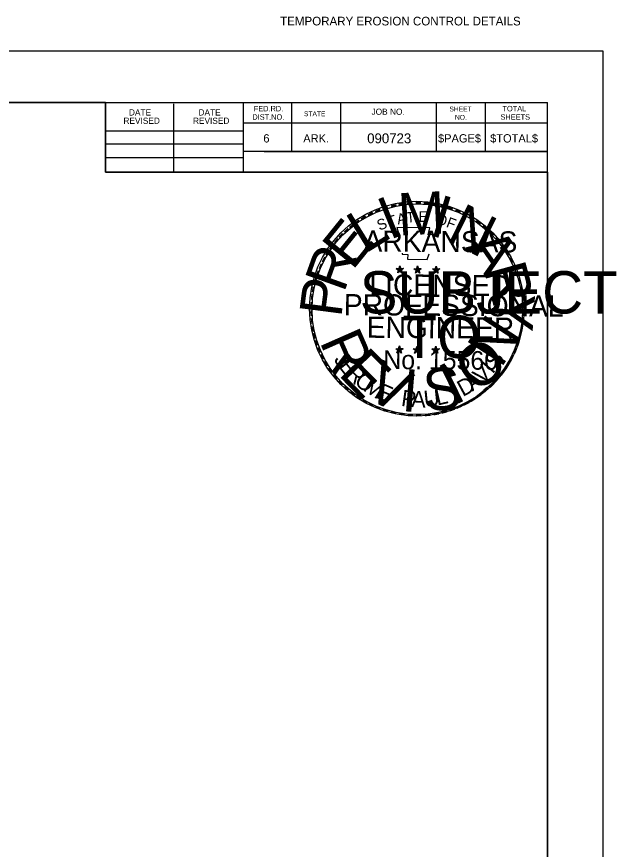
# Model space of a CAD drawing. Extents: x 60284.6 to 60318.8, y 53662.9 to 53686.5.
# Drawn here: x 60310.3 to 60318.8, y 53674.66 to 53686.45 of the extents above; entities that cross this region are included whole.
import ezdxf

# ---------------------------------------------------------------- set-up
doc = ezdxf.new("R2010")
doc.units = 0
for name, color, linetype in [('Level 1', 7, 'Continuous'), ('Level 38', 7, 'Continuous'), ('Level 49', 7, 'Continuous'), ('Level 62', 7, 'Continuous'), ('Level 63', 7, 'Continuous'), ('R_Border', 7, 'Continuous'), ('R_No Plot', 7, 'Continuous'), ('Stamp Mask', 7, 'Continuous'), ('TYPICAL FONT', 7, 'Continuous')]:
    doc.layers.add(name, color=color, linetype=linetype)

msp = doc.modelspace()

# ---------------------------------------------------------------- linework, layer by layer
at = {"layer": 'Level 1'}
for p, q in [((60286.201, 53685.237), (60317.819, 53685.237)), ((60311.555, 53684.249), (60311.555, 53685.237)), ((60312.523, 53684.249), (60312.523, 53685.217)), ((60313.509, 53685.237), (60313.509, 53684.249)), ((60314.193, 53685.237), (60314.193, 53684.543)), ((60314.887, 53685.237), (60314.887, 53684.543)), ((60316.245, 53685.237), (60316.245, 53684.543)), ((60316.939, 53685.237), (60316.939, 53684.543)), ((60317.819, 53664.691), (60317.819, 53685.237)), ((60311.555, 53684.835), (60313.509, 53684.835)), ((60317.819, 53684.943), (60313.509, 53684.943)), ((60317.819, 53684.945), (60317.819, 53684.945)), ((60311.555, 53684.649), (60313.509, 53684.649)), ((60317.819, 53684.543), (60313.509, 53684.543)), ((60313.805, 53684.543), (60317.819, 53684.543)), ((60311.555, 53684.455), (60313.509, 53684.455)), ((60317.819, 53684.249), (60311.555, 53684.249))]:
    msp.add_line(p, q, dxfattribs=at)
at = {"layer": 'Level 38'}
msp.add_lwpolyline([(60286.201, 53664.691), (60286.201, 53685.237), (60311.555, 53685.237), (60311.555, 53684.249), (60313.201, 53684.249), (60313.509, 53684.249), (60313.509, 53684.249), (60313.509, 53684.249), (60317.819, 53684.249), (60317.819, 53683.957), (60317.819, 53680.626), (60317.819, 53664.691)], close=True, dxfattribs=at)
at = {"layer": 'Level 49'}
for p, q in [((60315.676, 53682.883), (60315.73, 53682.866)), ((60315.676, 53682.883), (60315.715, 53682.881)), ((60315.676, 53682.883), (60315.715, 53682.879)), ((60315.676, 53682.883), (60315.711, 53682.874)), ((60315.676, 53682.883), (60315.711, 53682.868)), ((60315.676, 53682.883), (60315.711, 53682.866)), ((60315.676, 53682.883), (60315.711, 53682.861)), ((60315.698, 53682.822), (60315.73, 53682.866)), ((60315.698, 53682.822), (60315.711, 53682.864)), ((60315.698, 53682.822), (60315.715, 53682.859)), ((60315.698, 53682.822), (60315.717, 53682.857)), ((60315.698, 53682.822), (60315.722, 53682.853)), ((60315.698, 53682.822), (60315.73, 53682.853)), ((60315.698, 53682.822), (60315.73, 53682.85)), ((60315.73, 53682.924), (60315.722, 53682.883)), ((60315.73, 53682.924), (60315.722, 53682.887)), ((60315.73, 53682.924), (60315.726, 53682.887)), ((60315.73, 53682.866), (60315.73, 53682.924)), ((60315.73, 53682.924), (60315.739, 53682.883)), ((60315.73, 53682.924), (60315.737, 53682.887)), ((60315.73, 53682.924), (60315.732, 53682.887)), ((60315.782, 53682.883), (60315.73, 53682.866)), ((60315.761, 53682.82), (60315.73, 53682.866)), ((60315.761, 53682.82), (60315.73, 53682.853)), ((60315.761, 53682.82), (60315.73, 53682.85)), ((60315.782, 53682.883), (60315.733, 53682.879)), ((60315.761, 53682.82), (60315.733, 53682.853)), ((60315.782, 53682.883), (60315.739, 53682.875)), ((60315.782, 53682.883), (60315.739, 53682.872)), ((60315.761, 53682.82), (60315.739, 53682.864)), ((60315.761, 53682.82), (60315.739, 53682.859)), ((60315.761, 53682.82), (60315.745, 53682.866)), ((60315.782, 53682.883), (60315.746, 53682.872)), ((60315.782, 53682.883), (60315.752, 53682.868)), ((60315.782, 53682.883), (60315.754, 53682.866)), ((60315.926, 53682.881), (60315.979, 53682.866)), ((60315.926, 53682.881), (60315.964, 53682.879)), ((60315.926, 53682.881), (60315.964, 53682.875)), ((60315.926, 53682.881), (60315.964, 53682.874)), ((60315.926, 53682.881), (60315.963, 53682.866)), ((60315.926, 53682.881), (60315.963, 53682.864)), ((60315.926, 53682.881), (60315.963, 53682.859)), ((60315.948, 53682.82), (60315.979, 53682.866)), ((60315.948, 53682.82), (60315.964, 53682.861)), ((60315.948, 53682.82), (60315.964, 53682.859)), ((60315.948, 53682.82), (60315.966, 53682.857)), ((60315.948, 53682.82), (60315.972, 53682.851)), ((60315.948, 53682.82), (60315.979, 53682.851)), ((60315.948, 53682.82), (60315.979, 53682.85)), ((60315.979, 53682.92), (60315.972, 53682.881)), ((60315.979, 53682.92), (60315.972, 53682.883)), ((60315.979, 53682.92), (60315.974, 53682.883)), ((60315.979, 53682.866), (60315.979, 53682.92)), ((60315.979, 53682.92), (60315.988, 53682.881)), ((60315.979, 53682.92), (60315.987, 53682.883)), ((60315.979, 53682.92), (60315.981, 53682.883)), ((60316.031, 53682.881), (60315.979, 53682.866)), ((60316.011, 53682.82), (60315.979, 53682.866)), ((60316.011, 53682.82), (60315.979, 53682.851)), ((60316.011, 53682.82), (60315.979, 53682.85)), ((60316.031, 53682.881), (60315.985, 53682.879)), ((60316.011, 53682.82), (60315.985, 53682.851)), ((60316.031, 53682.881), (60315.988, 53682.874)), ((60316.031, 53682.881), (60315.988, 53682.872)), ((60316.011, 53682.82), (60315.988, 53682.864)), ((60316.011, 53682.82), (60315.988, 53682.857)), ((60316.011, 53682.82), (60315.994, 53682.864)), ((60316.031, 53682.881), (60315.996, 53682.868)), ((60316.031, 53682.881), (60316.001, 53682.866)), ((60316.031, 53682.881), (60316.003, 53682.864)), ((60316.19, 53682.879), (60316.244, 53682.861)), ((60316.19, 53682.879), (60316.232, 53682.874)), ((60316.19, 53682.879), (60316.229, 53682.872)), ((60316.19, 53682.879), (60316.229, 53682.868)), ((60316.19, 53682.879), (60316.227, 53682.864)), ((60316.19, 53682.879), (60316.227, 53682.859)), ((60316.19, 53682.879), (60316.227, 53682.859)), ((60316.21, 53682.818), (60316.244, 53682.861)), ((60316.21, 53682.818), (60316.229, 53682.859)), ((60316.21, 53682.818), (60316.232, 53682.853)), ((60316.21, 53682.818), (60316.232, 53682.851)), ((60316.21, 53682.818), (60316.244, 53682.851)), ((60316.21, 53682.818), (60316.24, 53682.85)), ((60316.21, 53682.818), (60316.247, 53682.844)), ((60316.244, 53682.916), (60316.234, 53682.881)), ((60316.244, 53682.916), (60316.24, 53682.879)), ((60316.244, 53682.916), (60316.24, 53682.879)), ((60316.244, 53682.861), (60316.244, 53682.916)), ((60316.244, 53682.916), (60316.255, 53682.879)), ((60316.244, 53682.916), (60316.251, 53682.879)), ((60316.244, 53682.916), (60316.247, 53682.879)), ((60316.295, 53682.879), (60316.244, 53682.861)), ((60316.273, 53682.818), (60316.244, 53682.861)), ((60316.273, 53682.818), (60316.244, 53682.851)), ((60316.273, 53682.818), (60316.244, 53682.844)), ((60316.295, 53682.879), (60316.249, 53682.874)), ((60316.273, 53682.818), (60316.249, 53682.85)), ((60316.295, 53682.879), (60316.255, 53682.872)), ((60316.295, 53682.879), (60316.255, 53682.866)), ((60316.273, 53682.818), (60316.255, 53682.859)), ((60316.273, 53682.818), (60316.255, 53682.853)), ((60316.273, 53682.818), (60316.258, 53682.859)), ((60316.295, 53682.879), (60316.262, 53682.864)), ((60316.295, 53682.879), (60316.264, 53682.864)), ((60316.295, 53682.879), (60316.269, 53682.861)), ((60315.722, 53681.789), (60315.711, 53681.752)), ((60315.722, 53681.789), (60315.715, 53681.748)), ((60315.722, 53681.789), (60315.717, 53681.748)), ((60315.722, 53681.732), (60315.722, 53681.789)), ((60315.722, 53681.789), (60315.73, 53681.748)), ((60315.722, 53681.789), (60315.73, 53681.748)), ((60315.722, 53681.789), (60315.722, 53681.748)), ((60315.972, 53681.785), (60315.963, 53681.748)), ((60315.972, 53681.785), (60315.964, 53681.748)), ((60315.972, 53681.785), (60315.966, 53681.748)), ((60315.972, 53681.732), (60315.972, 53681.785)), ((60315.972, 53681.785), (60315.979, 53681.746)), ((60315.972, 53681.785), (60315.979, 53681.746)), ((60315.972, 53681.785), (60315.972, 53681.748)), ((60316.236, 53681.783), (60316.227, 53681.744)), ((60316.236, 53681.783), (60316.229, 53681.744)), ((60316.236, 53681.783), (60316.232, 53681.744)), ((60316.236, 53681.726), (60316.236, 53681.783)), ((60316.236, 53681.783), (60316.244, 53681.744)), ((60316.236, 53681.783), (60316.244, 53681.744)), ((60316.236, 53681.783), (60316.236, 53681.744)), ((60315.669, 53681.748), (60315.722, 53681.732)), ((60315.669, 53681.748), (60315.708, 53681.746)), ((60315.669, 53681.748), (60315.706, 53681.741)), ((60315.669, 53681.748), (60315.706, 53681.741)), ((60315.669, 53681.748), (60315.706, 53681.733)), ((60315.669, 53681.748), (60315.706, 53681.732)), ((60315.669, 53681.748), (60315.706, 53681.73)), ((60315.687, 53681.691), (60315.722, 53681.732)), ((60315.687, 53681.691), (60315.706, 53681.732)), ((60315.687, 53681.691), (60315.708, 53681.724)), ((60315.687, 53681.691), (60315.709, 53681.724)), ((60315.687, 53681.691), (60315.722, 53681.722)), ((60315.687, 53681.691), (60315.715, 53681.719)), ((60315.687, 53681.691), (60315.722, 53681.717)), ((60315.752, 53681.687), (60315.719, 53681.717)), ((60315.774, 53681.748), (60315.722, 53681.732)), ((60315.752, 53681.687), (60315.722, 53681.732)), ((60315.752, 53681.687), (60315.722, 53681.719)), ((60315.752, 53681.687), (60315.724, 53681.719)), ((60315.774, 53681.748), (60315.726, 53681.746)), ((60315.774, 53681.748), (60315.73, 53681.741)), ((60315.774, 53681.748), (60315.73, 53681.739)), ((60315.752, 53681.687), (60315.73, 53681.732)), ((60315.752, 53681.687), (60315.73, 53681.724)), ((60315.774, 53681.748), (60315.737, 53681.737)), ((60315.752, 53681.687), (60315.737, 53681.732)), ((60315.774, 53681.748), (60315.741, 53681.733)), ((60315.774, 53681.748), (60315.745, 53681.732)), ((60315.918, 53681.748), (60315.972, 53681.732)), ((60315.918, 53681.748), (60315.957, 53681.744)), ((60315.918, 53681.748), (60315.957, 53681.741)), ((60315.918, 53681.748), (60315.957, 53681.739)), ((60315.918, 53681.748), (60315.955, 53681.733)), ((60315.918, 53681.748), (60315.955, 53681.73)), ((60315.918, 53681.748), (60315.955, 53681.726)), ((60315.937, 53681.687), (60315.972, 53681.732)), ((60315.937, 53681.687), (60315.957, 53681.73)), ((60315.937, 53681.687), (60315.957, 53681.722)), ((60315.937, 53681.687), (60315.959, 53681.722)), ((60315.937, 53681.687), (60315.964, 53681.719)), ((60315.937, 53681.687), (60315.972, 53681.719)), ((60315.937, 53681.687), (60315.972, 53681.715)), ((60316.001, 53681.687), (60315.97, 53681.715)), ((60316.022, 53681.746), (60315.972, 53681.732)), ((60316.001, 53681.687), (60315.972, 53681.732)), ((60316.001, 53681.687), (60315.972, 53681.719)), ((60316.001, 53681.687), (60315.974, 53681.719)), ((60316.022, 53681.746), (60315.977, 53681.746)), ((60316.022, 53681.746), (60315.979, 53681.739)), ((60316.022, 53681.746), (60315.979, 53681.739)), ((60316.001, 53681.687), (60315.979, 53681.73)), ((60316.001, 53681.687), (60315.979, 53681.724)), ((60316.022, 53681.746), (60315.987, 53681.733)), ((60316.001, 53681.687), (60315.987, 53681.73)), ((60316.022, 53681.746), (60315.992, 53681.732)), ((60316.022, 53681.746), (60315.994, 53681.73)), ((60316.183, 53681.744), (60316.236, 53681.726)), ((60316.183, 53681.744), (60316.221, 53681.741)), ((60316.183, 53681.744), (60316.221, 53681.737)), ((60316.183, 53681.744), (60316.219, 53681.733)), ((60316.183, 53681.744), (60316.219, 53681.73)), ((60316.183, 53681.744), (60316.218, 53681.726)), ((60316.183, 53681.744), (60316.218, 53681.722)), ((60316.203, 53681.683), (60316.236, 53681.726)), ((60316.203, 53681.683), (60316.219, 53681.726)), ((60316.203, 53681.683), (60316.221, 53681.719)), ((60316.203, 53681.683), (60316.225, 53681.719)), ((60316.203, 53681.683), (60316.229, 53681.715)), ((60316.203, 53681.683), (60316.234, 53681.715)), ((60316.203, 53681.683), (60316.236, 53681.711)), ((60316.266, 53681.683), (60316.234, 53681.715)), ((60316.266, 53681.683), (60316.234, 53681.711)), ((60316.288, 53681.744), (60316.236, 53681.726)), ((60316.266, 53681.683), (60316.236, 53681.726)), ((60316.266, 53681.683), (60316.24, 53681.715)), ((60316.288, 53681.744), (60316.242, 53681.741)), ((60316.288, 53681.744), (60316.244, 53681.737)), ((60316.288, 53681.744), (60316.244, 53681.733)), ((60316.266, 53681.683), (60316.244, 53681.719)), ((60316.266, 53681.683), (60316.247, 53681.726)), ((60316.266, 53681.683), (60316.249, 53681.726)), ((60316.288, 53681.744), (60316.255, 53681.732)), ((60316.288, 53681.744), (60316.256, 53681.726)), ((60316.288, 53681.744), (60316.258, 53681.726))]:
    msp.add_line(p, q, dxfattribs=at)
for points in [[(60315.687, 53683.465), (60315.724, 53683.339)], [(60316.212, 53683.323), (60316.234, 53683.367), (60316.129, 53683.362), (60316.153, 53683.461), (60315.687, 53683.465)], [(60315.759, 53683.101), (60315.759, 53683.086), (60315.842, 53683.084), (60315.835, 53683.016), (60316.114, 53683.014), (60316.144, 53683.092)], [(60315.73, 53682.924), (60315.761, 53682.82), (60315.676, 53682.883), (60315.782, 53682.883), (60315.698, 53682.822), (60315.73, 53682.924)], [(60315.979, 53682.92), (60316.011, 53682.82), (60315.926, 53682.881), (60316.031, 53682.881), (60315.948, 53682.82), (60315.979, 53682.92)], [(60316.244, 53682.916), (60316.273, 53682.818), (60316.19, 53682.879), (60316.295, 53682.879), (60316.21, 53682.818), (60316.244, 53682.916)], [(60315.722, 53681.789), (60315.752, 53681.687), (60315.669, 53681.748), (60315.774, 53681.748), (60315.687, 53681.691), (60315.722, 53681.789)], [(60315.972, 53681.785), (60316.001, 53681.687), (60315.918, 53681.748), (60316.022, 53681.746), (60315.937, 53681.687), (60315.972, 53681.785)], [(60316.236, 53681.783), (60316.266, 53681.683), (60316.183, 53681.744), (60316.288, 53681.744), (60316.203, 53681.683), (60316.236, 53681.783)], [(60316.929, 53681.144), (60316.922, 53681.168), (60316.966, 53681.205)], [(60316.962, 53681.21), (60316.97, 53681.188), (60316.925, 53681.149)], [(60316.97, 53681.192), (60316.925, 53681.153)], [(60316.97, 53681.188), (60316.927, 53681.151)]]:
    msp.add_lwpolyline(points, dxfattribs=at)
for centre, radius in [((60315.731, 53682.865), 0.0258), ((60315.731, 53682.865), 0.0233), ((60315.731, 53682.865), 0.0216), ((60315.731, 53682.865), 0.0199), ((60315.731, 53682.865), 0.0173), ((60315.731, 53682.865), 0.0161), ((60315.731, 53682.865), 0.0148), ((60315.731, 53682.865), 0.0128), ((60315.731, 53682.865), 0.0112), ((60315.731, 53682.865), 0.0093), ((60315.731, 53682.865), 0.00742), ((60315.731, 53682.865), 0.00553), ((60315.731, 53682.865), 0.00444), ((60315.731, 53682.865), 0.00216), ((60315.981, 53682.864), 0.0258), ((60315.981, 53682.864), 0.0233), ((60315.981, 53682.864), 0.0216), ((60315.981, 53682.864), 0.0199), ((60315.981, 53682.864), 0.0173), ((60315.981, 53682.864), 0.0161), ((60315.981, 53682.864), 0.0148), ((60315.981, 53682.864), 0.0128), ((60315.981, 53682.864), 0.0112), ((60315.981, 53682.864), 0.0093), ((60315.981, 53682.864), 0.00742), ((60315.981, 53682.864), 0.00553), ((60315.981, 53682.864), 0.00444), ((60315.981, 53682.864), 0.00216), ((60316.245, 53682.86), 0.0258), ((60316.245, 53682.86), 0.0233), ((60316.245, 53682.86), 0.0216), ((60316.245, 53682.86), 0.0199), ((60316.245, 53682.86), 0.0173), ((60316.245, 53682.86), 0.0161), ((60316.245, 53682.86), 0.0148), ((60316.245, 53682.86), 0.0128), ((60316.245, 53682.86), 0.0112), ((60316.245, 53682.86), 0.0093), ((60316.245, 53682.86), 0.00742), ((60316.245, 53682.86), 0.00553), ((60316.245, 53682.86), 0.00444), ((60316.245, 53682.86), 0.00216), ((60315.722, 53681.731), 0.0258), ((60315.722, 53681.731), 0.0233), ((60315.722, 53681.731), 0.0216), ((60315.722, 53681.731), 0.0199), ((60315.722, 53681.731), 0.0173), ((60315.722, 53681.731), 0.0161), ((60315.722, 53681.731), 0.0148), ((60315.722, 53681.731), 0.0128), ((60315.722, 53681.731), 0.0112), ((60315.722, 53681.731), 0.0093), ((60315.722, 53681.731), 0.00742), ((60315.722, 53681.731), 0.00553), ((60315.722, 53681.731), 0.00444), ((60315.722, 53681.731), 0.00216), ((60315.972, 53681.73), 0.0258), ((60315.972, 53681.73), 0.0233), ((60315.972, 53681.73), 0.0216), ((60315.972, 53681.73), 0.0199), ((60315.972, 53681.73), 0.0173), ((60315.972, 53681.73), 0.0161), ((60315.972, 53681.73), 0.0148), ((60315.972, 53681.73), 0.0128), ((60315.972, 53681.73), 0.0112), ((60315.972, 53681.73), 0.0093), ((60315.972, 53681.73), 0.00742), ((60315.972, 53681.73), 0.00553), ((60315.972, 53681.73), 0.00444), ((60315.972, 53681.73), 0.00216), ((60316.237, 53681.726), 0.0258), ((60316.237, 53681.726), 0.0233), ((60316.237, 53681.726), 0.0216), ((60316.237, 53681.726), 0.0199), ((60316.237, 53681.726), 0.0173), ((60316.237, 53681.726), 0.0161), ((60316.237, 53681.726), 0.0148), ((60316.237, 53681.726), 0.0128), ((60316.237, 53681.726), 0.0112), ((60316.237, 53681.726), 0.0093), ((60316.237, 53681.726), 0.00742), ((60316.237, 53681.726), 0.00553), ((60316.237, 53681.726), 0.00444), ((60316.237, 53681.726), 0.00216)]:
    msp.add_circle(centre, radius, dxfattribs=at)
at = {"layer": 'Level 62'}
msp.add_circle((60315.976, 53682.306), 1.492, dxfattribs=at)
at = {"layer": 'Level 63'}
msp.add_lwpolyline([(60284.604, 53685.965), (60318.604, 53685.965), (60318.604, 53663.965), (60284.604, 53663.965)], close=True, dxfattribs=at)
at = {"layer": 'R_No Plot'}
msp.add_lwpolyline([(60317.819, 53674.964), (60317.819, 53684.249), (60311.555, 53684.249), (60311.555, 53685.237), (60286.201, 53685.237), (60286.201, 53664.691), (60303.668, 53664.691), (60317.819, 53664.691)], close=True, dxfattribs=at)
at = {"layer": 'Stamp Mask'}
msp.add_circle((60315.969, 53682.315), 1.521, dxfattribs=at)

# ---------------------------------------------------------------- texts
at = {"layer": 'Level 1'}
for s, height, p in [('TOTAL', 0.0782, (60317.183, 53685.109)), ('DATE', 0.0879, (60311.888, 53685.051)), ('DATE', 0.0879, (60312.874, 53685.051)), ('DIST.NO.', 0.0782, (60313.637, 53684.991)), ('FED.RD.', 0.0782, (60313.657, 53685.109)), ('STATE', 0.0684, (60314.369, 53685.041)), ('JOB NO.', 0.0879, (60315.327, 53685.061)), ('SHEET', 0.0684, (60316.431, 53685.109)), ('SHEETS', 0.0782, (60317.155, 53684.991)), ('REVISED', 0.0879, (60311.81, 53684.933)), ('REVISED', 0.0879, (60312.796, 53684.933)), ('NO.', 0.0684, (60316.509, 53684.991)), ('6', 0.117, (60313.793, 53684.669)), ('ARK.', 0.1172, (60314.359, 53684.669)), ('090723', 0.14, (60315.265, 53684.658)), ('$PAGE$', 0.1172, (60316.269, 53684.669)), ('$TOTAL$', 0.1172, (60317.008, 53684.669))]:
    msp.add_text(s, height=height, dxfattribs=at).set_placement(p)
at = {"layer": 'Level 49'}
for s, height, rotation, p in [('-', 0.24, 13.2326, (60315.611, 53683.672)), ('-', 0.24, 9.8217, (60315.711, 53683.696)), ('-', 0.24, 5.4992, (60315.822, 53683.711)), ('-', 0.24, 359.7886, (60315.937, 53683.722)), ('-', 0.24, 357.3454, (60316.048, 53683.718)), ('-', 0.24, 351.7641, (60316.157, 53683.709)), ('-', 0.24, 346.8073, (60316.266, 53683.692)), ('-', 0.24, 28.3942, (60315.308, 53683.55)), ('-', 0.24, 23.9096, (60315.403, 53683.596)), ('-', 0.24, 18.7785, (60315.499, 53683.637)), ('A', 0.15, 10.8156, (60315.7, 53683.506)), ('T', 0.15, 5.6252, (60315.828, 53683.53)), ('E', 0.15, 0.4347, (60315.992, 53683.544)), ('-', 0.24, 341.9386, (60316.36, 53683.666)), ('-', 0.24, 337.4575, (60316.469, 53683.633)), ('-', 0.24, 333.7235, (60316.565, 53683.594)), ('-', 0.24, 35.8341, (60315.131, 53683.437)), ('-', 0.24, 33.666, (60315.218, 53683.496)), ('S', 0.15, 21.1964, (60315.438, 53683.419)), ('T', 0.15, 16.006, (60315.575, 53683.469)), ('O', 0.15, 350.0539, (60316.232, 53683.513)), ('F', 0.15, 339.6731, (60316.375, 53683.476)), ('-', 0.24, 329.2433, (60316.65, 53683.55)), ('-', 0.24, 325.4651, (60316.746, 53683.493)), ('-', 0.24, 42.5646, (60314.994, 53683.319)), ('-', 0.24, 38.5531, (60315.061, 53683.38)), ('ARKANSAS', 0.2995, 359.6024, (60315.212, 53683.125)), ('-', 0.24, 320.1321, (60316.837, 53683.43)), ('-', 0.24, 315.181, (60316.927, 53683.356)), ('-', 0.24, 50.2166, (60314.865, 53683.177)), ('-', 0.24, 48.0254, (60314.926, 53683.249)), ('-', 0.24, 309.4821, (60317.01, 53683.273)), ('-', 0.24, 53.8349, (60314.802, 53683.092)), ('-', 0.24, 306.2546, (60317.086, 53683.182)), ('-', 0.24, 57.673, (60314.754, 53683.01)), ('-', 0.21, 303.2777, (60317.16, 53683.095)), ('-', 0.24, 67.3767, (60314.669, 53682.829)), ('-', 0.24, 62.4738, (60314.708, 53682.92)), ('-', 0.24, 299.2708, (60317.206, 53683.005)), ('-', 0.24, 71.9969, (60314.634, 53682.735)), ('-', 0.24, 294.2652, (60317.254, 53682.912)), ('-', 0.24, 290.1752, (60317.295, 53682.829)), ('-', 0.24, 75.0634, (60314.604, 53682.628)), ('LICENSED', 0.2995, 359.6024, (60315.296, 53682.505)), ('-', 0.24, 284.7257, (60317.326, 53682.741)), ('-', 0.24, 80.8037, (60314.582, 53682.522)), ('-', 0.24, 280.1517, (60317.356, 53682.628)), ('-', 0.24, 84.7887, (60314.571, 53682.419)), ('PROFESSIONAL', 0.29945, 359.6024, (60314.933, 53682.223)), ('-', 0.24, 276.1986, (60317.382, 53682.513)), ('-', 0.24, 88.6646, (60314.567, 53682.314)), ('-', 0.24, 273.9325, (60317.389, 53682.404)), ('-', 0.24, 93.7983, (60314.571, 53682.205)), ('-', 0.24, 269.5431, (60317.393, 53682.312)), ('-', 0.24, 98.5503, (60314.582, 53682.103)), ('ENGINEER', 0.2995, 359.6024, (60315.257, 53681.903)), ('-', 0.24, 263.1196, (60317.389, 53682.212)), ('-', 0.24, 101.3173, (60314.599, 53681.994)), ('-', 0.24, 260.5977, (60317.376, 53682.114)), ('-', 0.24, 105.0602, (60314.625, 53681.905)), ('-', 0.24, 255.365, (60317.36, 53682.012)), ('-', 0.24, 108.6898, (60314.656, 53681.813)), ('-', 0.24, 113.6667, (60314.693, 53681.72)), ('-', 0.24, 252.4705, (60317.334, 53681.903)), ('-', 0.24, 115.3313, (60314.739, 53681.628)), ('J', 0.231, 303.9209, (60314.785, 53681.593)), ('No. 15560', 0.2635, 359.6024, (60315.493, 53681.46)), ('S', 0.231, 53.5227, (60317.099, 53681.446)), ('-', 0.24, 244.2221, (60317.258, 53681.709)), ('-', 0.24, 247.4911, (60317.301, 53681.802)), ('-', 0.24, 120.0495, (60314.791, 53681.539)), ('E', 0.231, 308.618, (60314.85, 53681.496)), ('V', 0.231, 41.4844, (60316.889, 53681.235)), ('I', 0.231, 49.9999, (60317.042, 53681.38)), ('-', 0.24, 238.6736, (60317.199, 53681.598)), ('-', 0.24, 125.4958, (60314.852, 53681.456)), ('R', 0.231, 314.7784, (60314.946, 53681.378)), ('-', 0.24, 233.4476, (60317.142, 53681.501)), ('-', 0.24, 130.3205, (60314.918, 53681.373)), ('-', 0.24, 133.8262, (60314.996, 53681.292)), ('O', 0.231, 321.6761, (60315.069, 53681.259)), ('M', 0.231, 328.1357, (60315.196, 53681.162)), ('D', 0.231, 28.5809, (60316.621, 53681.063)), ('A', 0.231, 34.8903, (60316.757, 53681.139)), ('-', 0.24, 233.4476, (60317.071, 53681.419)), ('-', 0.24, 138.5362, (60315.072, 53681.221)), ('E', 0.231, 336.4966, (60315.375, 53681.059)), ('-', 0.24, 225.3677, (60317.001, 53681.332)), ('-', 0.24, 144.2487, (60315.159, 53681.16)), ('-', 0.24, 147.6922, (60315.24, 53681.103)), ('P', 0.231, 351.9783, (60315.738, 53680.94)), ('A', 0.231, 357.9896, (60315.886, 53680.921)), ('U', 0.231, 5.7635, (60316.078, 53680.919)), ('L', 0.231, 13.0992, (60316.258, 53680.941)), ('-', 0.24, 215.3387, (60316.839, 53681.186)), ('-', 0.24, 151.1728, (60315.325, 53681.055)), ('-', 0.24, 154.2026, (60315.406, 53681.016)), ('-', 0.24, 203.854, (60316.582, 53681.031)), ('-', 0.24, 206.9592, (60316.676, 53681.077)), ('-', 0.24, 211.8515, (60316.759, 53681.129)), ('-', 0.24, 158.1636, (60315.499, 53680.976)), ('-', 0.24, 162.4007, (60315.602, 53680.944)), ('-', 0.24, 167.1579, (60315.708, 53680.92)), ('-', 0.24, 172.7179, (60315.822, 53680.904)), ('-', 0.24, 185.4191, (60316.168, 53680.905)), ('-', 0.24, 190.8882, (60316.279, 53680.924)), ('-', 0.24, 195.0767, (60316.388, 53680.953)), ('-', 0.24, 200.3208, (60316.489, 53680.99)), ('-', 0.24, 176.1207, (60315.935, 53680.893)), ('-', 0.24, 181.1942, (60316.046, 53680.896))]:
    msp.add_text(s, height=height, rotation=rotation, dxfattribs=at).set_placement(p)
at = {"layer": 'Level 62'}
for s, rotation, p in [('I', 22.0105, (60315.58, 53683.284)), ('M', 2.6943, (60315.712, 53683.35)), ('I', 343.3781, (60316.132, 53683.362)), ('N', 333.7199, (60316.369, 53683.285)), ('L', 31.6686, (60315.232, 53683.087)), ('E', 50.9849, (60315.055, 53682.846)), ('A', 304.7456, (60316.651, 53683.182)), ('R', 70.3011, (60314.935, 53682.529)), ('R', 285.4294, (60316.912, 53682.877)), ('P', 82.6089, (60314.896, 53682.18)), ('Y', 266.1131, (60317.047, 53682.553)), ('N', 57.1378, (60317.161, 53681.461)), ('R', 293.7639, (60314.584, 53681.851)), ('O', 36.5754, (60316.798, 53681.106)), ('E', 314.3262, (60314.842, 53681.383)), ('V', 334.8885, (60315.214, 53681.058)), ('I', 26.2943, (60316.492, 53680.938)), ('I', 355.4508, (60315.742, 53680.866)), ('S', 5.732, (60316.09, 53680.855))]:
    msp.add_text(s, height=0.6, rotation=rotation, dxfattribs=at).set_placement(p)
for s, p in [('SUBJECT', (60315.16, 53682.246)), ('TO', (60315.766, 53681.616))]:
    msp.add_text(s, height=0.6, dxfattribs=at).set_placement(p)
at = {"layer": 'R_Border'}
msp.add_text('JOB NO.', height=0.0879, dxfattribs=at).set_placement((60315.327, 53685.061))
at = {"layer": 'TYPICAL FONT'}
msp.add_text('TEMPORARY EROSION CONTROL DETAILS', height=0.1224, dxfattribs=at).set_placement((60314.031, 53686.327))

doc.saveas('drawing.dxf')
